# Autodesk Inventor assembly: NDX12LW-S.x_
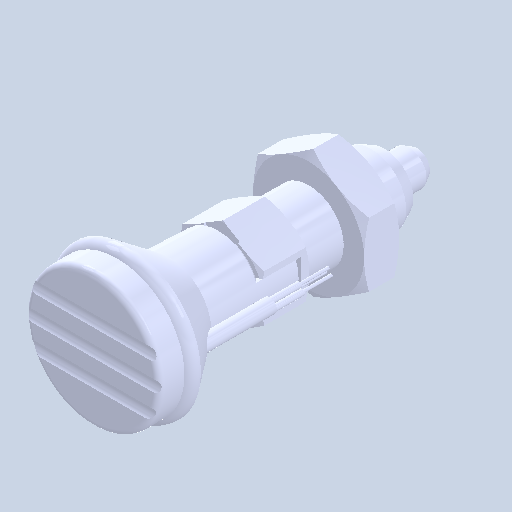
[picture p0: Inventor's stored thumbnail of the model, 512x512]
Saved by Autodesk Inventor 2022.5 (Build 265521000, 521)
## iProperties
Created: 2024-05
Part Number: NDX12LW-S.x_
Document SubType Name: Assembly
Designer: ImaoCorp
Author: ImaoCorp
Sending System: SOLIDWORKS 2022-2022290
MC: AMD64
MC_MODEL: Intel64 Family 6 Model 60 Stepping 3, GenuineIntel
OS: Windows_NT
FRU: Parasolid Version 33.1, build 260,  4-25-2022
FORMAT: text
GUISE: transmit
KEY: FILENDX12LW-S.x_t
DATE: Tue May 21 08:47:57 2024
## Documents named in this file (3)
- X:\14_SW2022-Inv2022\保留中\kipp\KME_データ\n\ndx12lw-s\NDX12LW-S.x_.iam
- X:\14_SW2022-Inv2022\保留中\kipp\KME_データ\n\ndx12lw-s\NDX12LW-S_01.ipt
- X:\14_SW2022-Inv2022\保留中\kipp\KME_データ\n\ndx12lw-s\NDX12LW-S_02.ipt
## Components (2 placed, 2 different names)
1. NDX12LW-S_01
2. NDX12LW-S_02
